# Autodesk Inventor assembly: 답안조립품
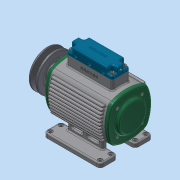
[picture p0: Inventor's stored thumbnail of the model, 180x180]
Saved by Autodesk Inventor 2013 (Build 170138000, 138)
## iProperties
Created: 2015-11
Part Number: 답안조립품
Document SubType Name: Assembly
Designer: dgall
Author: dgall
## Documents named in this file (18)
- C:\Users\dgall\Desktop\351109V1018\답안조립품.iam
- C:\Users\dgall\Desktop\351109V1018\본체.ipt
- C:\Users\dgall\Desktop\351109V1018\뒷커버.ipt
- C:\Users\dgall\Desktop\351109V1018\앞커버.ipt
- C:\Users\dgall\Desktop\351109V1018\베어링 6203.ipt
- C:\Users\dgall\Desktop\351109V1018\오일실 17 30 8.ipt
- C:\Users\dgall\Desktop\351109V1018\볼트 M4 x 12.ipt
- C:\Users\dgall\Desktop\351109V1018\축.ipt
- C:\Users\dgall\Desktop\351109V1018\부시.ipt
- C:\Users\dgall\Desktop\351109V1018\헤더커버.ipt
- C:\Users\dgall\Desktop\351109V1018\볼트 M4 x 16.ipt
- C:\Users\dgall\Desktop\351109V1018\V-벨트풀리.ipt
- C:\Users\dgall\Desktop\351109V1018\키 - 5 x 5 x 18.ipt
- C:\Users\dgall\Desktop\351109V1018\멈춤나사 M4x5.ipt
- C:\Users\dgall\Desktop\351109V1018\슬라이드.ipt
- C:\Users\dgall\Desktop\351109V1018\스프링1.ipt
- C:\Users\dgall\Desktop\351109V1018\스프링2.ipt
- C:\Users\dgall\Desktop\351109V1018\스프링3.ipt
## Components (4 placed, 3 different names)
1. 7-베어링 6203:1
2. 7-베어링 6203:2
3. 헤더커버:1
4. V-벨트풀리:1
